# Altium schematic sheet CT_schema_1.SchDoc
size 601 x 258 mm
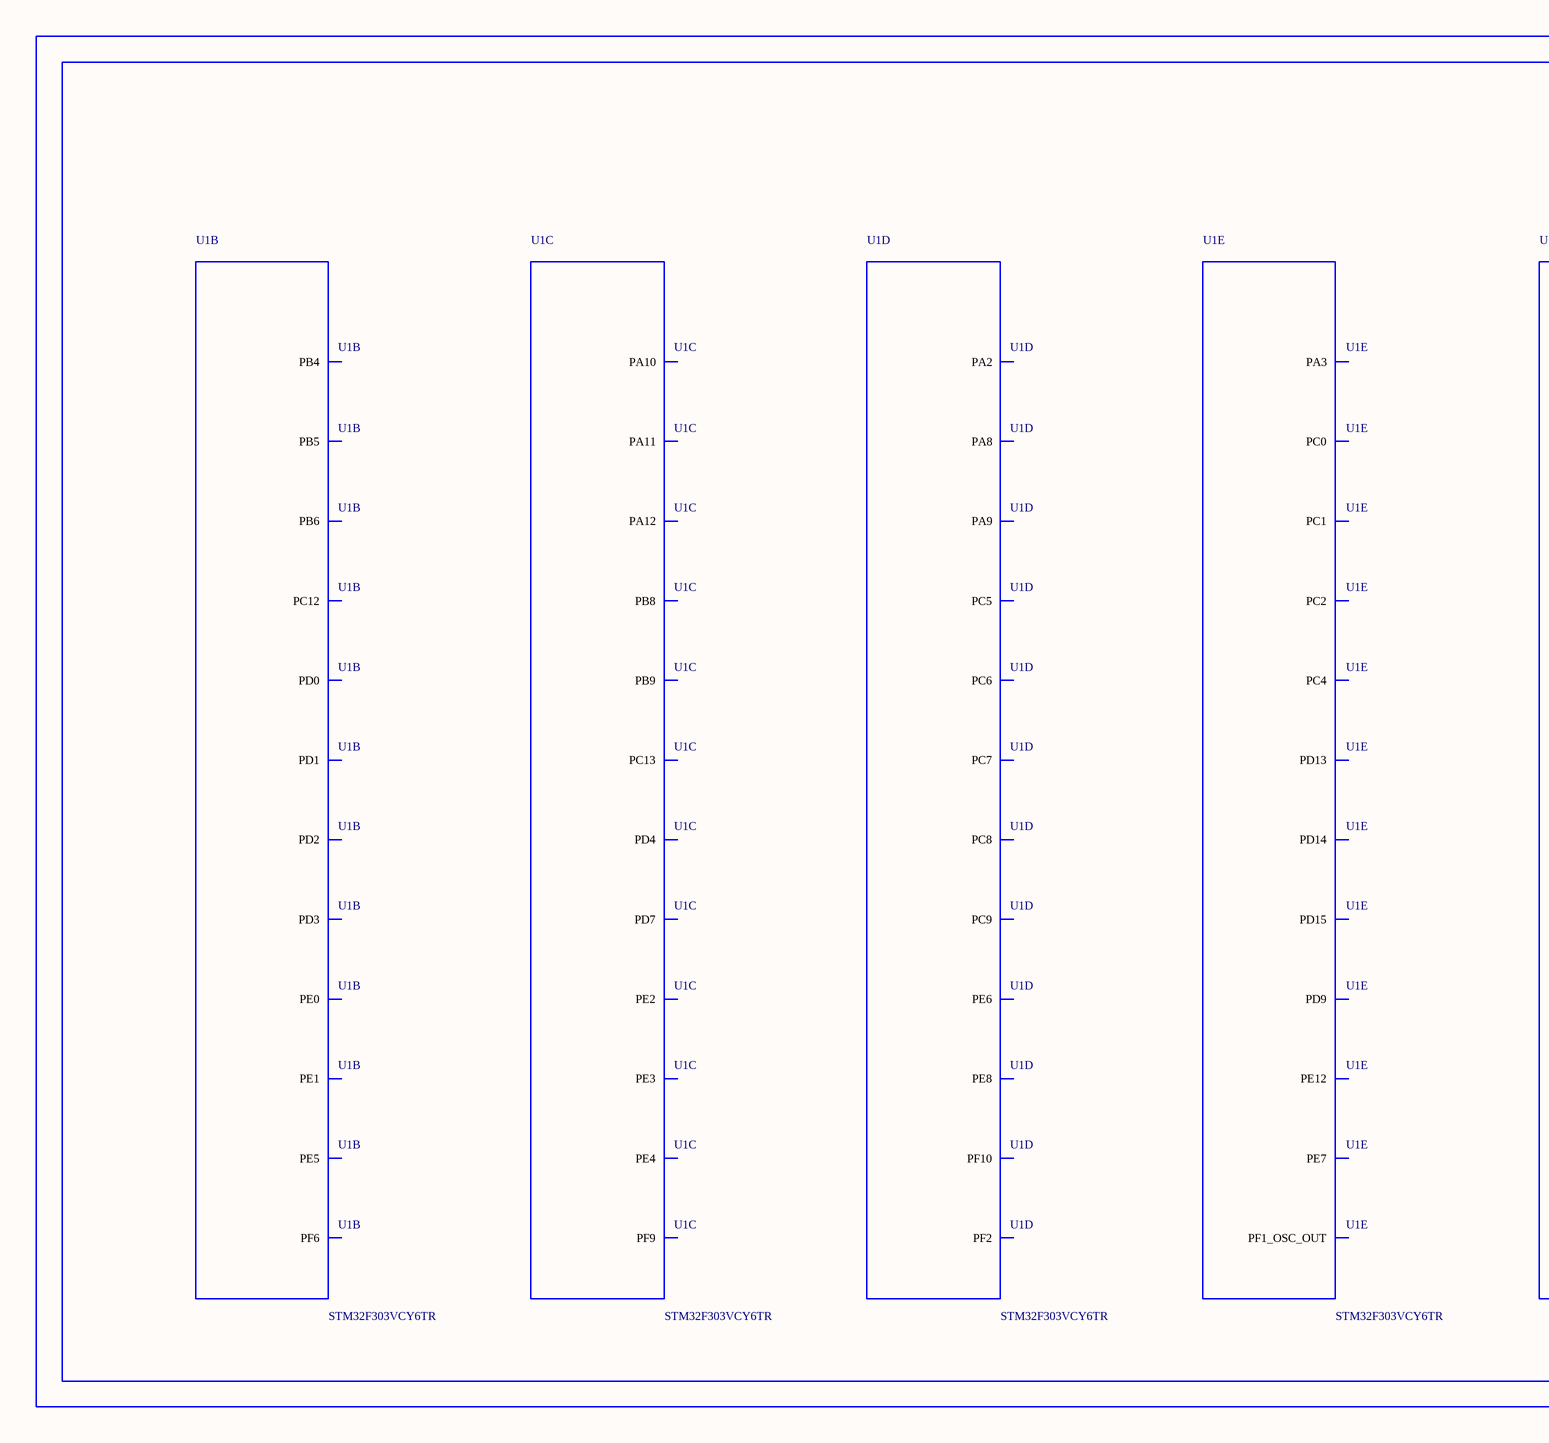
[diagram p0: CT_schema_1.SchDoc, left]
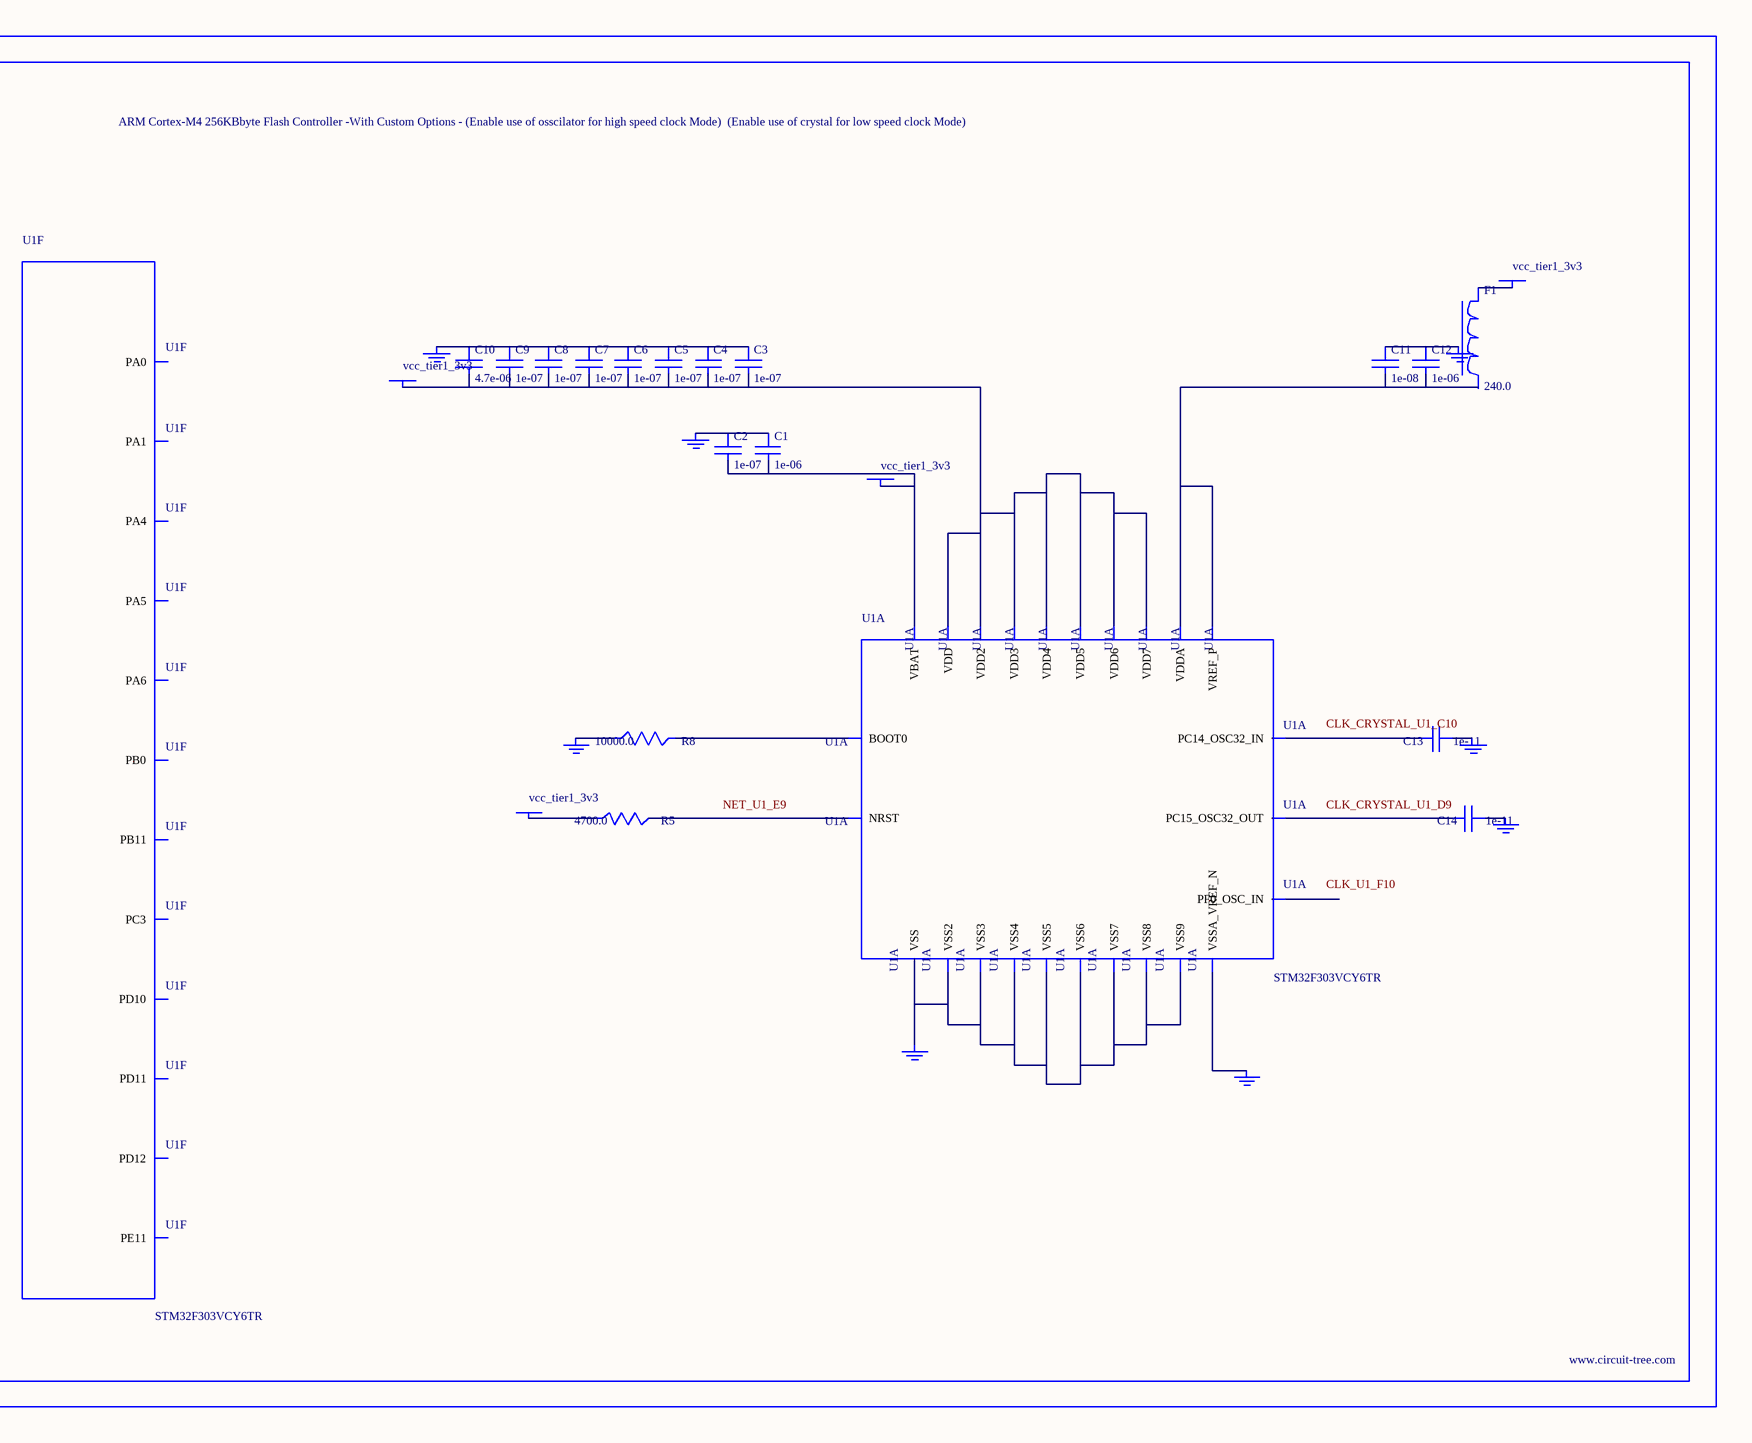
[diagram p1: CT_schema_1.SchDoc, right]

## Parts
BORDER0  (no value)
C1  1e-06  [C0603]
C2  1e-07  [C0603]
C3  1e-07  [C0603]
C4  1e-07  [C0603]
C5  1e-07  [C0603]
C6  1e-07  [C0603]
C7  1e-07  [C0603]
C8  1e-07  [C0603]
C9  1e-07  [C0603]
C10  4.7e-06  [C0603]
C11  1e-08  [C0603]
C12  1e-06  [C0603]
C13  1e-11  [C0402]
C14  1e-11  [C0402]
F1  240.0  [L0603]
GND_INSTANCE_0_0  (no value)
GND_INSTANCE_0_1  (no value)
GND_INSTANCE_0_2  (no value)
GND_INSTANCE_0_3  (no value)
GND_INSTANCE_0_4  (no value)
GND_INSTANCE_0_5  (no value)
GND_INSTANCE_0_6  (no value)
GND_INSTANCE_0_7  (no value)
POWER_INSTANCE_0_0  vcc_tier1_3v3
POWER_INSTANCE_0_1  vcc_tier1_3v3
POWER_INSTANCE_0_2  vcc_tier1_3v3
POWER_INSTANCE_0_3  vcc_tier1_3v3
R5  4700.0  [R0603]
R8  10000.0  [R0603]
U1  STM32F303VCY6TR  [WLCSP100]  (parts A,B,C,D,E,F of 10)

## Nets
NetC1_1: C1.1 C2.1 GND_INSTANCE_0_0.0(GND)
NetC1_2: C1.2 C2.2 POWER_INSTANCE_0_0.0(PWR) U1.D8(VBAT)
NetC3_1: C3.1 C4.1 C5.1 C6.1 C7.1 C8.1 C9.1 C10.1 GND_INSTANCE_0_2.0(GND)
NetC3_2: C3.2 C4.2 C5.2 C6.2 C7.2 C8.2 C9.2 C10.2 POWER_INSTANCE_0_2.0(PWR) U1.A9(VDD2) U1.A10(VDD) U1.B8(VDD4) U1.B10(VDD3) U1.D2(VDD5) U1.J5(VDD6) U1.K8(VDD7)
NetC11_1: C11.1 C12.1 GND_INSTANCE_0_1.0(GND)
NetC11_2: C11.2 C12.2 U1.J8(VREF_P) U1.J10(VDDA)
NetC13_1: C13.1 GND_INSTANCE_0_4.0(GND)
NetC13_2: C13.2 U1.C10(PC14_OSC32_IN)
NetC14_1: C14.1 GND_INSTANCE_0_5.0(GND)
NetC14_2: C14.2 U1.D9(PC15_OSC32_OUT)
NetF1_1: F1.1 POWER_INSTANCE_0_1.0(PWR)
NetGND_INSTANCE_0_3_0: GND_INSTANCE_0_3.0(GND) R8.1
NetGND_INSTANCE_0_6_0: GND_INSTANCE_0_6.0(GND) U1.H8(VSSA_VREF_N)
NetGND_INSTANCE_0_7_0: GND_INSTANCE_0_7.0(GND) U1.A1(VSS) U1.A2(VSS2) U1.B1(VSS3) U1.C7(VSS4) U1.J1(VSS5) U1.K1(VSS6) U1.K2(VSS8) U1.K9(VSS9) U1.K10(VSS7)
NetPOWER_INSTANCE_0_3_0: POWER_INSTANCE_0_3.0(PWR) R5.1
NetR5_2: R5.2 U1.E9(NRST)
NetR8_2: R8.2 U1.A7(BOOT0)

Not connected (* = marked no-connect by the designer): F1 2; U1 A3(PC12) A4(PD2) A6(PB5) A8(PE1) B3(PD0) B4(PD3) B5(PB4) B6(PB6) B7(PE0) B9(PE5) C1(PF6) C3(PD1) C4(PD4) C6(PB9) C8(PE4) C9(PC13) D1(PA12) D4(PD7) D5(PB8) D6(PE2) D7(PE3) D10(PF9) E1(PA10) E2(PA11) E5(PA9) E6(PE8) E7(PE6) E8(PF2) E10(PF10) F1(PC8) F2(PC7) F3(PC9) F4(PC6) F5(PA8) F6(PC5) F7(PA2) F8(PE7) F9(PF1_OSC_OUT) F10(PF0_OSC_IN) G1(PD15) G2(PD14) G3(PD13) G4(PD9) G5(PE12) G6(PC4) G7(PA3) G8(PC2) G9(PC1) G10(PC0) H1(PD12) H2(PD11) H3(PD10) H5(PE11) H6(PA6) H7(PA5) H9(PA0) H10(PC3) J6(PB0) J7(PA4) J9(PA1) K3(PB11)

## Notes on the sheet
- Labels drawn without touching a wire or pin: CLK_CRYSTAL_U1_C10, CLK_CRYSTAL_U1_D9, CLK_U1_F10, NET_U1_E9

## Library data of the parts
BORDER0 = BORDER_PAGE0
C1 C12 = C0603C105K3RACTU
C2-C9 = 06035C104K4Z2A
C10 = GRM188R6YA475KE15D
C11 = 06035C103K4Z2A
C13 C14 = C0402C100K3GACTU
F1 = Z0603C241ASMST
GND_INSTANCE_0_0-GND_INSTANCE_0_7 = GND
POWER_INSTANCE_0_0-POWER_INSTANCE_0_3 = PWR
R5 = RC0603JR-074K7L
R8 = RC0603JR-0710KL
